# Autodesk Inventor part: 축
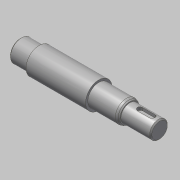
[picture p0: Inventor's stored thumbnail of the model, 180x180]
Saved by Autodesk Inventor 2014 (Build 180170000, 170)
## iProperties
Created: 2016-06
Part Number: 축
Material: 강철, 연강
Document SubType Name: Modeling
Designer: mduedu
Density: 7.86 g/cm^3
Appearance: 강철
Author: mduedu
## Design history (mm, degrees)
sketch "스케치1"
  geometry: L1 (-63, 0)-(63, 0); L2 (-63, 0)-(-63, 10); L3 (-63, 10)-(-46, 10); L4 (-46, 10)-(-46, 12); L5 (-46, 12)-(8, 12); L6 (8, 12)-(8, 10); L7 (8, 10)-(36, 10); L8 (36, 10)-(36, 8); L9 (36, 8)-(63, 8); L10 (63, 8)-(63, 0); 2 further points
  constraints: 20 end point, 5 parallel, 2 perpendicular, 1 coincident, 1 collinear, 1 horizontal, 1 midpoint, 1 vertical
  dimensions: "d0" = 126 distance of L1.start L1.end; "d2" = 16 diameter of L9 L1; "d3" = 20 diameter of L7 L1; "d4" = 24 diameter of L5 L1; "d5" = 20 diameter of L3 L1; "d6" = 17 distance of L2.end L3.end; "d7" = 27 distance of L8.end L9.end; "d8" = 55 distance from line of L5.end L10
revolve "회전1" sketch "스케치1" stored, may be unused: angle "d9" = 90 deg
chamfer "모따기1" distance "d10" = 2; stored, may be unused: second distance "d11" = 2, angle "d12" = 30 deg
fillet "모깎기1" dims "d13" = 4
node "작업 평면1"
sketch "스케치2"
  geometry: L1 (-4, 2.5)-(7, 2.5); L2 (7, -2.5)-(-4, -2.5); L3 (-4, 0)-(7, 0); L4 (-13.5, 8.845)-(-13.5, -8.845) reference; A1 r 2.5 centre (-4, 0) between (-4, 2.5) and (-4, -2.5); A2 r 2.5 centre (7, 0) between (7, -2.5) and (7, 2.5); 1 further point
  constraints: 6 end point, 4 point on circle, 3 tangent, 2 centre point, 2 parallel, 1 horizontal, 1 horizontal alignment
  dimensions: "d14" = 7 distance edge to line of A1 L4; "d15" = 5 distance between parallel lines of L2 L1; "d16" = 16 dimension on A2 A1
extrude "돌출1" cut sketch "스케치2" distance "d17" = 3; taper "d18" = 0 deg
chamfer "모따기2" distance "d19" = 1; stored, may be unused: second distance "d20" = 2, angle "d21" = 30 deg
sketch "스케치3"
  geometry: L1 (-36, -8)-(-62, -8) reference; L2 (-63, -7)-(-63, 7) reference; L3 (-39.5, -8)-(-41, -6.5); L4 (-41, -6.5)-(-41, -8); L5 (-39.5, -8)-(-41, -8); 1 further point
  constraints: 6 end point, 2 point on line, 1 collinear, 1 vertical
  dimensions: "d22" = 45 deg angle of L4 L3; "d23" = 22 distance between parallel lines of L2 L4; "d24" = 3 diameter of L3.start L4
revolve "회전2" stored, may be unused: angle "d25" = 90 deg
node "작업점1"
sketch "스케치4"
  geometry: 1 further point
hole "구멍1" sketch "스케치4" at (0, 0) diameter "d26" = 3.242; stored, may be unused: countersink angle "d30" = 90 deg, drill point angle "d32" = 120 deg; dims "d27" = 8, "d28" = 4, "d29" = 2, "d31" = 11
chamfer "모따기3" distance "d33" = 2; stored, may be unused: second distance "d34" = 2, angle "d35" = 30 deg
node "솔리드1"
